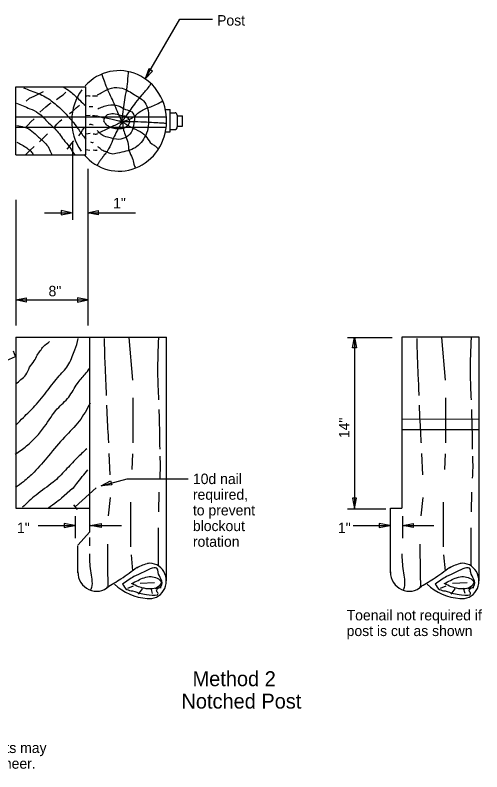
# Model space of a CAD drawing. Extents: x -0.7 to 88.8, y -25.9 to 22.
# Drawn here: x 70.1 to 76.35, y -25.09 to -14.95 of the extents above; entities that cross this region are included whole.
import ezdxf

# ---------------------------------------------------------------- set-up
doc = ezdxf.new("R2010")
doc.units = 0
doc.layers.add('Default', color=7, linetype='Continuous')

msp = doc.modelspace()

# ---------------------------------------------------------------- linework, layer by layer
at = {"layer": 'Default'}
for p, q in [((71.04331375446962, -16.823761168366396), (71.04331375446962, -15.91392783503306)), ((70.10589708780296, -15.914594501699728), (71.04431375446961, -15.914594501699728)), ((70.10589708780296, -16.823761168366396), (70.10589708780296, -15.914594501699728)), ((71.08914708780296, -16.177094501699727), (71.13923042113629, -16.175427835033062)), ((72.11214708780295, -16.216427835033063), (72.17239708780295, -16.216427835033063)), ((72.17239708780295, -16.516927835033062), (72.17239708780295, -16.216427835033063)), ((70.09814708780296, -16.314261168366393), (72.12131375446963, -16.314261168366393)), ((71.04739708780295, -16.29659450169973), (71.10381375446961, -16.29259450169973)), ((72.12489708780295, -16.311094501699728), (72.12489708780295, -16.311094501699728)), ((72.17239708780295, -16.259094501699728), (72.24081375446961, -16.259094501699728)), ((72.26614708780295, -16.29342783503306), (72.26739708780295, -16.446927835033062)), ((72.26614708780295, -16.299761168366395), (72.33731375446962, -16.299761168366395)), ((72.33731375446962, -16.43992783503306), (72.33731375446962, -16.299761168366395)), ((70.09814708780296, -16.452761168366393), (72.12131375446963, -16.452761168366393)), ((72.11214708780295, -16.516927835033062), (72.17239708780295, -16.516927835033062)), ((72.17239708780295, -16.483427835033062), (72.23198042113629, -16.483427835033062)), ((72.26731375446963, -16.43992783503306), (72.33731375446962, -16.43992783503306)), ((71.04739708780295, -16.54192783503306), (71.10148042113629, -16.533594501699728)), ((70.86614708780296, -16.658427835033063), (70.86614708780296, -17.693427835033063)), ((70.10589708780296, -16.823761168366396), (71.04331375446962, -16.823761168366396)), ((71.04331375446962, -16.754261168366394), (71.09964708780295, -16.760927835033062)), ((71.07373042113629, -17.009427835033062), (71.07373042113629, -18.68392783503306)), ((70.10589708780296, -17.42659450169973), (70.10589708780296, -18.68392783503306)), ((70.48964708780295, -17.598927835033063), (70.85448042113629, -17.598927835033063)), ((71.06806375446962, -17.598927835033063), (71.70896236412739, -17.598927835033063)), ((70.10589708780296, -18.68392783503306), (70.10589708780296, -19.109261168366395)), ((71.07373042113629, -18.68392783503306), (71.07373042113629, -19.109261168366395)), ((70.10698042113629, -18.767094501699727), (71.07373042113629, -18.767094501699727)), ((70.10556375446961, -19.26442783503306), (70.10556375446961, -21.55459450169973)), ((70.10556375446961, -19.26442783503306), (72.12564708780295, -19.26459450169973)), ((71.09181375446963, -19.26442783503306), (71.09181375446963, -21.876261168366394)), ((71.62181375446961, -19.27042783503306), (71.66898042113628, -19.843094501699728)), ((72.12564708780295, -22.53142783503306), (72.12564708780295, -19.26459450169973)), ((74.54789708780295, -19.269094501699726), (75.14773042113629, -19.269094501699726)), ((74.64239708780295, -19.269094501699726), (74.64239708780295, -20.435761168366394)), ((75.27839708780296, -19.26442783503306), (75.27839708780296, -21.55459450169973)), ((76.31223042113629, -19.26459450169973), (75.27839708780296, -19.26442783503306)), ((75.80839708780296, -19.27042783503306), (75.85556375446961, -19.843094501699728)), ((76.31223042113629, -22.53142783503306), (76.31223042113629, -19.26459450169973)), ((70.10106375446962, -19.522927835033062), (70.07406375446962, -19.453594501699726)), ((69.81464708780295, -19.649594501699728), (70.10414708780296, -19.523261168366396)), ((71.67639708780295, -20.076594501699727), (71.67639708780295, -20.681261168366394)), ((75.86298042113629, -20.076594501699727), (75.86298042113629, -20.681261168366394)), ((75.27839708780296, -20.363511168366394), (76.31331375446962, -20.360261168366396)), ((74.64239708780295, -20.435761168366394), (74.64239708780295, -20.69392783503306)), ((75.27839708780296, -20.504344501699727), (76.31273042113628, -20.50109450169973)), ((74.64239708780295, -20.69392783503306), (74.64239708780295, -21.56359450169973)), ((71.35281375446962, -20.823261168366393), (71.36514708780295, -21.110761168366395)), ((71.67148042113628, -20.830927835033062), (71.66231375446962, -21.040261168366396)), ((75.53939708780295, -20.823261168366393), (75.55173042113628, -21.110761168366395)), ((75.85806375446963, -20.830927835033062), (75.84889708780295, -21.040261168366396)), ((71.24931375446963, -21.257927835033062), (71.59981375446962, -21.165261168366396)), ((71.59981375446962, -21.165261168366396), (72.41406375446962, -21.165261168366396)), ((70.90231375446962, -21.539761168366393), (71.18273042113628, -21.28609450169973)), ((70.50306375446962, -21.290094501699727), (70.50306375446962, -21.290094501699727)), ((70.86789708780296, -21.295094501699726), (70.71998042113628, -21.422594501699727)), ((72.02456375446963, -21.341594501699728), (72.01689708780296, -21.606761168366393)), ((76.21114708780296, -21.341594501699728), (76.20348042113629, -21.606761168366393)), ((71.37106375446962, -21.415761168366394), (71.34573042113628, -21.65792783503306)), ((71.64281375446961, -21.47792783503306), (71.64281375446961, -22.07542783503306)), ((75.55764708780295, -21.415761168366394), (75.53231375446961, -21.65792783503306)), ((75.82939708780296, -21.47792783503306), (75.82939708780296, -22.07542783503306)), ((70.10556375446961, -21.55459450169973), (71.09714708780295, -21.55459450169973)), ((70.93364708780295, -21.57409450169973), (70.88273042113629, -21.51292783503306)), ((74.54789708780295, -21.56359450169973), (74.87214708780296, -21.56359450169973)), ((74.87214708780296, -21.56359450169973), (75.06131375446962, -21.56359450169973)), ((75.12389708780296, -22.345761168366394), (75.12389708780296, -21.55459450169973)), ((75.12389708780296, -21.55459450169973), (75.27839708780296, -21.55459450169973)), ((70.90173042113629, -21.662261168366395), (70.90173042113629, -21.958927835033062)), ((75.28431375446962, -21.662261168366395), (75.28431375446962, -21.958927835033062)), ((70.40514708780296, -21.789594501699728), (70.89456375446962, -21.789594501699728)), ((71.10806375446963, -21.789594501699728), (71.52239708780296, -21.789594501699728)), ((74.62473042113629, -21.789594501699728), (75.11414708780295, -21.789594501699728)), ((75.28931375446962, -21.789594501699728), (75.70364708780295, -21.789594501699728)), ((71.09181375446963, -21.876261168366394), (70.94406375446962, -22.04692783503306)), ((71.09181375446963, -21.94742783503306), (71.09181375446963, -22.061261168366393)), ((70.93731375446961, -22.345761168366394), (70.93731375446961, -22.05892783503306)), ((70.94406375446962, -22.054094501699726), (70.94406375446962, -22.04692783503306)), ((71.64998042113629, -22.181427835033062), (71.66973042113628, -22.395594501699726)), ((75.83656375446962, -22.181427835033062), (75.85631375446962, -22.395594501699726)), ((70.93731375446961, -22.424094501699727), (70.93731375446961, -22.345761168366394)), ((75.12389708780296, -22.424094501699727), (75.12389708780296, -22.345761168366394)), ((71.60914708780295, -22.630261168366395), (71.68314708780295, -22.594761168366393)), ((71.77048042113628, -22.559261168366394), (71.96531375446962, -22.552094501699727)), ((72.05264708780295, -22.54492783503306), (72.04673042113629, -22.510261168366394)), ((75.79573042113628, -22.630261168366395), (75.86973042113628, -22.594761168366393)), ((75.95706375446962, -22.559261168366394), (76.15189708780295, -22.552094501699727)), ((76.23923042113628, -22.54492783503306), (76.23331375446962, -22.510261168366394)), ((71.75023042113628, -22.70859450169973), (71.80406375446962, -22.637427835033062)), ((71.93839708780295, -22.701427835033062), (71.91823042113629, -22.630261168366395)), ((72.05339708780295, -22.62392783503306), (71.97273042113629, -22.631094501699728)), ((71.97273042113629, -22.631094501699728), (72.01231375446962, -22.630261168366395)), ((75.93681375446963, -22.70859450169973), (75.99064708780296, -22.637427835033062)), ((76.12498042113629, -22.701427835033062), (76.10481375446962, -22.630261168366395)), ((76.23998042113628, -22.62392783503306), (76.15931375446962, -22.631094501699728)), ((76.15931375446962, -22.631094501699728), (76.19889708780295, -22.630261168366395))]:
    msp.add_line(p, q, dxfattribs=at)
for points in [[(71.83831375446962, -15.805011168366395), (72.30406375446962, -15.006094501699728), (72.74331375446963, -15.006094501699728)], [(70.24564708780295, -16.104261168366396), (70.29156375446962, -16.066761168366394), (70.35206375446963, -16.035761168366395), (70.42514708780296, -16.00259450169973), (70.47739708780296, -15.973927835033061)], [(70.65273042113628, -16.08209450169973), (70.70706375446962, -16.04242783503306), (70.74048042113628, -16.01809450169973), (70.77806375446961, -15.98492783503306)], [(70.42931375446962, -16.25242783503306), (70.47114708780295, -16.217094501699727), (70.50873042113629, -16.17942783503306), (70.56089708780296, -16.137427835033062), (70.58173042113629, -16.126261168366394)], [(70.82823042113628, -16.272261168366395), (70.87206375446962, -16.23692783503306), (70.91589708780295, -16.194927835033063), (70.96189708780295, -16.157261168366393)], [(70.24348042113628, -16.446927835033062), (70.27064708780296, -16.422594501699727), (70.30823042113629, -16.382761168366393), (70.35206375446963, -16.342927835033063)], [(70.62564708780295, -16.45359450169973), (70.65689708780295, -16.413761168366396), (70.69873042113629, -16.371761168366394), (70.72381375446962, -16.35192783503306)], [(70.94931375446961, -16.568594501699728), (70.97639708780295, -16.533261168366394), (70.99948042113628, -16.49342783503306), (71.02656375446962, -16.455761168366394)], [(70.42514708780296, -16.65042783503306), (70.46689708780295, -16.603927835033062), (70.53173042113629, -16.544261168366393)], [(70.23306375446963, -16.827261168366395), (70.29573042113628, -16.765261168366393), (70.35206375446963, -16.712261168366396)], [(70.79689708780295, -16.747594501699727), (70.82606375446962, -16.71009450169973), (70.8512304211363, -16.672427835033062), (70.8824804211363, -16.63709450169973)]]:
    msp.add_lwpolyline(points, dxfattribs=at)
for points in [[(71.88875710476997, -15.67144669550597), (71.83831375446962, -15.805011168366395), (71.9362477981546, -15.701122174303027)], [(70.71448042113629, -17.62692783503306), (70.85448042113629, -17.598927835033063), (70.71448042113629, -17.57092783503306)], [(71.20806375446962, -17.62692783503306), (71.06806375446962, -17.598927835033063), (71.20806375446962, -17.57092783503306)], [(70.24698042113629, -18.79509450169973), (70.10698042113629, -18.767094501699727), (70.24698042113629, -18.73909450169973)], [(70.93373042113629, -18.795208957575), (71.07373042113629, -18.767208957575), (70.93373042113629, -18.739208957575)], [(74.61439708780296, -19.409094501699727), (74.64239708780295, -19.269094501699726), (74.67039708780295, -19.409094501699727)], [(71.39160823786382, -21.246253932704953), (71.24931375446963, -21.257927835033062), (71.37617254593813, -21.19242327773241)], [(74.61439708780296, -21.42359450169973), (74.64239708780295, -21.56359450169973), (74.67039708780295, -21.42359450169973)], [(70.75456375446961, -21.817594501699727), (70.89456375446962, -21.789594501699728), (70.75456375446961, -21.76159450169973)], [(71.24806375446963, -21.817594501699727), (71.10806375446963, -21.789594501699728), (71.24806375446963, -21.76159450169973)], [(74.97414708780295, -21.817594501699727), (75.11414708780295, -21.789594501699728), (74.97414708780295, -21.76159450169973)], [(75.42931375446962, -21.817594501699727), (75.28931375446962, -21.789594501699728), (75.42931375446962, -21.76159450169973)]]:
    msp.add_lwpolyline(points, close=True, dxfattribs=at)
for centre, major_axis, ratio, start_param, end_param in [((71.49134795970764, -16.369057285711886), (1.9067660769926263e-16, 0.6731102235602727), 0.9445438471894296, 2.3036393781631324, 7.079119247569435), ((71.49134795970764, -16.369057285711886), (1.9067660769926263e-16, 0.6731102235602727), 0.9445438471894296, 0.9008811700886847, 2.2143986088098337), ((72.23805967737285, -16.28938255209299), (8.495526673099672e-18, 0.029990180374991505), 0.9445438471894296, 4.574533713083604, 6.237265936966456), ((72.23916784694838, -16.288575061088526), (-4.793224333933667e-18, -0.0298063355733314), 0.9445438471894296, 1.4313513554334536, 1.4392111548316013), ((72.23693875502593, -16.451785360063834), (-5.240425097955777e-18, -0.03258722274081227), 0.9445438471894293, 6.0937818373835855, 8.002272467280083), ((71.97049453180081, -22.797490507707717), (1.4392587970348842e-16, 0.5080748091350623), 0.9445438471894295, 0.17943739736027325, 0.5303528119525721), ((71.89890567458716, -22.53128149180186), (6.704483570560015e-17, 0.23667593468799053), 0.9445438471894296, 2.997306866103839, 6.4059503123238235), ((76.15707786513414, -22.797490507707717), (1.4392587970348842e-16, 0.5080748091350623), 0.9445438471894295, 0.17943739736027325, 0.5303528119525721), ((76.08548900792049, -22.53128149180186), (6.704483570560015e-17, 0.23667593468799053), 0.9445438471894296, 2.997306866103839, 6.4059503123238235), ((71.18664795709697, -22.40607036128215), (-4.245406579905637e-17, -0.2639976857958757), 0.9445438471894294, 4.7265868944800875, 7.018322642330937), ((75.3732312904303, -22.40607036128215), (-4.245406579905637e-17, -0.2639976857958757), 0.9445438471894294, 4.7265868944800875, 7.018322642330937), ((71.91306372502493, -21.986540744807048), (-1.254338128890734e-16, -0.7800015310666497), 0.9445438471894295, 5.5640474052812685, 6.222034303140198), ((76.09964705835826, -21.986540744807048), (-1.254338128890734e-16, -0.7800015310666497), 0.9445438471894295, 5.5640474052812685, 6.222034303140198)]:
    msp.add_ellipse(centre, major_axis=major_axis, ratio=ratio, start_param=start_param, end_param=end_param, dxfattribs=at)
for points in [[(71.52981375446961, -16.369594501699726), (71.54023042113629, -16.278927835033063), (71.55698042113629, -16.148594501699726), (71.57781375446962, -16.024594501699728), (71.60289708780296, -15.872261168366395), (71.61123042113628, -15.772761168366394), (71.61748042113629, -15.708594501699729)], [(71.52773042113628, -16.37392783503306), (71.49014708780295, -16.294427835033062), (71.44623042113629, -16.188261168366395), (71.40039708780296, -16.08442783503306), (71.35231375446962, -15.98492783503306), (71.30848042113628, -15.876594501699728), (71.29589708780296, -15.838927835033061), (71.25831375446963, -15.74392783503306)], [(71.53189708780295, -16.371761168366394), (71.57989708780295, -16.31209450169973), (71.65089708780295, -16.212594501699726), (71.71573042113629, -16.124094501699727), (71.80123042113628, -16.01809450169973), (71.84514708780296, -15.967261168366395), (71.89314708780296, -15.907594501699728), (71.91606375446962, -15.869927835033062)], [(70.21014708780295, -15.927427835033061), (70.31239708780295, -15.96492783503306), (70.50239708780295, -16.04692783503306), (70.65273042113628, -16.157261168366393), (70.79689708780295, -16.29659450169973), (70.93048042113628, -16.460261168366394), (71.02656375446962, -16.590594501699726), (71.04706375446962, -16.61559450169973)], [(70.74048042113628, -15.914094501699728), (70.83448042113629, -15.973927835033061), (70.96398042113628, -16.093261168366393), (71.04414708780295, -16.16542783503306)], [(71.20198042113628, -16.020261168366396), (71.26881375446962, -15.982594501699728), (71.38781375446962, -15.929594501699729), (71.53189708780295, -15.931927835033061), (71.69689708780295, -16.01809450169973), (71.81589708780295, -16.09992783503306), (71.87231375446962, -16.197094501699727), (71.88481375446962, -16.33642783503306), (71.87639708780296, -16.471261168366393), (71.83264708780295, -16.588427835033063), (71.76573042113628, -16.679094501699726), (71.68431375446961, -16.740927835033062), (71.57989708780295, -16.77642783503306), (71.46931375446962, -16.802761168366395), (71.38781375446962, -16.811761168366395), (71.32314708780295, -16.785261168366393), (71.27298042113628, -16.767594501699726), (71.22281375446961, -16.72992783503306), (71.20398042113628, -16.716594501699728)], [(71.04739708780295, -16.03142783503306), (71.09756375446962, -16.03142783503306), (71.10389708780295, -16.03159450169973)], [(71.13523042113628, -16.03242783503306), (71.17481375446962, -16.033594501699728), (71.19989708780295, -16.03142783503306)], [(71.53398042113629, -16.37392783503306), (71.65298042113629, -16.33642783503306), (71.77206375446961, -16.24359450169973), (71.91398042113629, -16.17942783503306), (71.99548042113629, -16.144094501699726), (72.07481375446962, -16.102094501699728)], [(70.11648042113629, -16.133094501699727), (70.29573042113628, -16.205927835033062), (70.40848042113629, -16.26342783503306), (70.54414708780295, -16.39392783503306), (70.64448042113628, -16.486761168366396), (70.7634804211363, -16.643594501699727), (70.84706375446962, -16.749927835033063), (70.89498042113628, -16.818261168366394), (70.90339708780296, -16.825094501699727)], [(71.20398042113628, -16.208261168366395), (71.27089708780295, -16.17942783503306), (71.34606375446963, -16.15959450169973), (71.47964708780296, -16.166094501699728), (71.57573042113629, -16.214761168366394), (71.65931375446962, -16.24809450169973), (71.69689708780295, -16.340761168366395), (71.68639708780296, -16.40492783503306), (71.66556375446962, -16.499927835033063), (71.59248042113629, -16.581761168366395), (71.48806375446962, -16.61709450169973), (71.35439708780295, -16.592927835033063), (71.27298042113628, -16.564094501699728), (71.22498042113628, -16.526594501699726), (71.20198042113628, -16.499927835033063)], [(71.13523042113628, -16.29559450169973), (71.16231375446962, -16.298761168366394), (71.20198042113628, -16.298761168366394)], [(71.52773042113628, -16.376261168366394), (71.45048042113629, -16.365094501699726), (71.3794804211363, -16.347427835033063), (71.28756375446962, -16.329761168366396), (71.22914708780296, -16.31659450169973), (71.20823042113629, -16.30992783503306)], [(71.28756375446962, -16.376261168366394), (71.30223042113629, -16.318761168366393), (71.33556375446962, -16.285594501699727), (71.41498042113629, -16.272261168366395), (71.51106375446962, -16.292261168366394), (71.60706375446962, -16.32759450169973), (71.62798042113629, -16.387261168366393), (71.57573042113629, -16.45792783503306), (71.50473042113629, -16.475761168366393), (71.41914708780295, -16.471261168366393), (71.35439708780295, -16.444761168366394), (71.31056375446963, -16.40942783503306), (71.2917304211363, -16.376261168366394)], [(71.09506375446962, -16.416094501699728), (71.11223042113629, -16.413761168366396), (71.14181375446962, -16.420927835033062)], [(71.53398042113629, -16.376261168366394), (71.48806375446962, -16.455761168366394), (71.46089708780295, -16.506761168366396), (71.41289708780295, -16.603927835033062), (71.39198042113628, -16.656927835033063), (71.33348042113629, -16.769761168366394), (71.31264708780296, -16.800594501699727), (71.2917304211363, -16.825094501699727), (71.26256375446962, -16.86709450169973), (71.23331375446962, -16.904594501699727), (71.21448042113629, -16.93559450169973), (71.20198042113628, -16.95542783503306), (71.19573042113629, -16.959761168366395)], [(71.52773042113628, -16.37392783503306), (71.48381375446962, -16.40492783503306), (71.41706375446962, -16.435927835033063), (71.30848042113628, -16.48892783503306), (71.23123042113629, -16.524261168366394), (71.20198042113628, -16.53542783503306)], [(71.52773042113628, -16.376261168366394), (71.64256375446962, -16.449261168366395), (71.77206375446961, -16.513261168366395), (71.86181375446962, -16.592927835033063), (71.92656375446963, -16.674594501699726), (71.96831375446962, -16.70109450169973), (72.00589708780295, -16.73442783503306), (72.02264708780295, -16.743094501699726)], [(71.53189708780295, -16.376261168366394), (71.70106375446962, -16.37842783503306), (71.85764708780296, -16.382761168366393), (71.98714708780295, -16.391761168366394), (72.07273042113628, -16.39609450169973), (72.12281375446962, -16.40042783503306)], [(71.53189708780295, -16.376261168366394), (71.54656375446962, -16.471261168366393), (71.56948042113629, -16.555261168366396), (71.60706375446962, -16.654761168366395), (71.62381375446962, -16.769761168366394), (71.66556375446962, -16.864761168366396), (71.68848042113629, -16.946594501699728), (71.70939708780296, -17.00409450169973)], [(70.12181375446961, -16.430761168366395), (70.29981375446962, -16.48892783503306), (70.3854804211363, -16.56192783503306), (70.49206375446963, -16.656927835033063), (70.55048042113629, -16.73442783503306), (70.58598042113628, -16.811761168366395), (70.59639708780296, -16.827261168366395)], [(71.14306375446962, -16.54192783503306), (71.14348042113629, -16.54192783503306), (71.19364708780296, -16.544261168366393), (71.19989708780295, -16.54192783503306)], [(70.11964708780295, -16.652761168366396), (70.25606375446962, -16.732094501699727), (70.30614708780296, -16.77409450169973), (70.34164708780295, -16.825094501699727)], [(71.10606375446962, -16.65142783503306), (71.13098042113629, -16.656927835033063), (71.14748042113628, -16.655261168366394)], [(71.14348042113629, -16.756594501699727), (71.18314708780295, -16.760927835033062), (71.19781375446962, -16.75859450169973)], [(70.10689708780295, -19.895594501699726), (70.17598042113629, -19.834094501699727), (70.24131375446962, -19.77259450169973), (70.29223042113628, -19.668761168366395), (70.35398042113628, -19.584094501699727), (70.39389708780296, -19.50709450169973), (70.43389708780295, -19.44942783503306), (70.47748042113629, -19.391761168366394), (70.56039708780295, -19.325761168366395)], [(70.11048042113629, -20.441761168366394), (70.20864708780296, -20.341761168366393), (70.36123042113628, -20.18792783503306), (70.53556375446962, -19.97642783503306), (70.68814708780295, -19.784094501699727), (70.81889708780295, -19.622594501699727), (70.86248042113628, -19.52642783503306), (70.89889708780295, -19.43792783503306), (70.94131375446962, -19.285261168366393)], [(71.28931375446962, -19.28292783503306), (71.30014708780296, -19.635594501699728), (71.31356375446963, -19.92009450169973), (71.31798042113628, -20.047594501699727)], [(72.01723042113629, -19.275094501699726), (72.00564708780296, -19.742261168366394), (72.01806375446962, -20.10492783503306)], [(75.47589708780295, -19.28292783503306), (75.48673042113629, -19.635594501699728), (75.50014708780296, -19.92009450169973), (75.50456375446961, -20.047594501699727)], [(76.20381375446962, -19.275094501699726), (76.19223042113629, -19.742261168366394), (76.20464708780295, -20.10492783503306)], [(70.09964708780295, -20.834094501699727), (70.25223042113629, -20.722594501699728), (70.49198042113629, -20.464761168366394), (70.66264708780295, -20.22642783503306), (70.81531375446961, -20.068594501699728), (70.93156375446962, -19.88792783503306), (71.03698042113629, -19.761094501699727), (71.09248042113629, -19.686761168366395)], [(71.10314708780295, -20.149594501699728), (70.95539708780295, -20.39142783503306), (70.76056375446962, -20.60492783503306), (70.54548042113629, -20.853927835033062), (70.35064708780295, -21.074261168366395), (70.20956375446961, -21.20242783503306), (70.10198042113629, -21.280761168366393)], [(71.32248042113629, -20.175594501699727), (71.32698042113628, -20.304094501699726), (71.34714708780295, -20.674094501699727), (71.34748042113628, -20.68092783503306)], [(72.02256375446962, -20.23292783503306), (72.02573042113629, -20.32559450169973), (72.03431375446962, -20.766261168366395)], [(75.50906375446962, -20.175594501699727), (75.51356375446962, -20.304094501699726), (75.53373042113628, -20.674094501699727), (75.53406375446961, -20.68092783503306)], [(76.20914708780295, -20.23292783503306), (76.21231375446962, -20.32559450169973), (76.22089708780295, -20.766261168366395)], [(71.05614708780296, -20.76142783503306), (70.92173042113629, -20.88942783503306), (70.77389708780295, -21.045927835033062), (70.60589708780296, -21.20942783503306), (70.37748042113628, -21.380261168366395), (70.19614708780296, -21.54542783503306)], [(72.03614708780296, -20.858594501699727), (72.03923042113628, -21.015594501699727), (72.03439708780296, -21.152761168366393)], [(76.22273042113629, -20.858594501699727), (76.22581375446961, -21.015594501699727), (76.22098042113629, -21.152761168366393)], [(70.86789708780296, -21.295094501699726), (70.92431375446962, -21.22642783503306), (71.07031375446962, -21.041761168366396)], [(70.54639708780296, -21.553427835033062), (70.65539708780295, -21.468594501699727), (70.71998042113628, -21.422594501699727)], [(72.01306375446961, -21.820261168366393), (72.01306375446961, -22.033594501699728), (72.01306375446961, -22.282594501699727), (72.01306375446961, -22.325261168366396)], [(76.19964708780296, -21.820261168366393), (76.19964708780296, -22.033594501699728), (76.19964708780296, -22.282594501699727), (76.19964708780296, -22.325261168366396)], [(71.33364708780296, -22.039927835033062), (71.33364708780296, -22.210594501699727), (71.34039708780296, -22.594761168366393)], [(75.52023042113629, -22.039927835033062), (75.52023042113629, -22.210594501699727), (75.52698042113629, -22.594761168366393)], [(71.09181375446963, -22.167927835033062), (71.09181375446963, -22.189261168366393), (71.11189708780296, -22.424094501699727), (71.11189708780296, -22.64459450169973), (71.10523042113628, -22.658761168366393)], [(75.27839708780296, -22.167927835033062), (75.27839708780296, -22.189261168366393), (75.29848042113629, -22.424094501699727), (75.29848042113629, -22.64459450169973), (75.29181375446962, -22.658761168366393)], [(71.32698042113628, -22.616094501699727), (71.51506375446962, -22.502261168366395), (71.73331375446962, -22.346094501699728)], [(71.53531375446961, -22.573427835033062), (71.68981375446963, -22.473761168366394), (71.82423042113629, -22.409761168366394), (72.00564708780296, -22.374261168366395), (72.01306375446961, -22.417761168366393), (72.05339708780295, -22.510261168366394), (72.05339708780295, -22.602594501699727), (71.99298042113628, -22.65959450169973), (72.01231375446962, -22.701427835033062), (71.89131375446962, -22.715594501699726), (71.78389708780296, -22.701427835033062), (71.66973042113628, -22.66592783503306), (71.59573042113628, -22.64459450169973), (71.53531375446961, -22.573427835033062)], [(75.51356375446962, -22.616094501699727), (75.70164708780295, -22.502261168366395), (75.91989708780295, -22.346094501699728)], [(75.72189708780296, -22.573427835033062), (75.87639708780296, -22.473761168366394), (76.01081375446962, -22.409761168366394), (76.19223042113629, -22.374261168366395), (76.19964708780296, -22.417761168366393), (76.23998042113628, -22.510261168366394), (76.23998042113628, -22.602594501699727), (76.17956375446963, -22.65959450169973), (76.19889708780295, -22.701427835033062), (76.07789708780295, -22.715594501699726), (75.97048042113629, -22.701427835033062), (75.85631375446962, -22.66592783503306), (75.78231375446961, -22.64459450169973), (75.72189708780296, -22.573427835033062)], [(71.65623042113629, -22.566261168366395), (71.74356375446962, -22.523594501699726), (71.82423042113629, -22.487927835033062), (71.91823042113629, -22.473761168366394), (71.99889708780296, -22.49509450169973), (72.05264708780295, -22.54492783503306), (72.02573042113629, -22.60192783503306), (71.93839708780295, -22.637427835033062), (71.82423042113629, -22.630261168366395), (71.75023042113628, -22.60892783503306), (71.66289708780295, -22.566261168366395)], [(75.84281375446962, -22.566261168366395), (75.93014708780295, -22.523594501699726), (76.01081375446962, -22.487927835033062), (76.10481375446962, -22.473761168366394), (76.18548042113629, -22.49509450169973), (76.23923042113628, -22.54492783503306), (76.21231375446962, -22.60192783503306), (76.12498042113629, -22.637427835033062), (76.01081375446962, -22.630261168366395), (75.93681375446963, -22.60892783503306), (75.84948042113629, -22.566261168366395)]]:
    msp.add_spline(points, degree=3, dxfattribs=at)

# ---------------------------------------------------------------- texts
for s, height, p in [('Post', 0.13999999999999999, (72.80267767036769, -15.092495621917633)), ('1"', 0.13999999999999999, (71.40994991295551, -17.539998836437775)), ('8" ', 0.13999999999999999, (70.54544113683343, -18.71873325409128)), ('10d nail ', 0.13999999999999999, (72.47874736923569, -21.233857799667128)), ('required, ', 0.13999999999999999, (72.47874736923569, -21.44385779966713)), ('to prevent ', 0.13999999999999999, (72.47874736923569, -21.653857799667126)), ('1"', 0.13999999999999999, (70.12325142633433, -21.889279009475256)), ('blockout ', 0.13999999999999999, (72.47874736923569, -21.863857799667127)), ('1" ', 0.13999999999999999, (74.42186748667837, -21.889279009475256)), ('rotation', 0.13999999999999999, (72.47874736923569, -22.073857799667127)), ('Toenail not required if', 0.13999999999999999, (74.53784741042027, -23.059740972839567)), ('post is cut as shown', 0.13999999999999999, (74.53784741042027, -23.269740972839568)), ('  Method 2', 0.19999999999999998, (72.32531203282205, -23.941090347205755)), ('Notched Post', 0.19999999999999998, (72.32531203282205, -24.241090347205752)), ('Alternate methods of placing the Blockouts on round Posts may', 0.13999999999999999, (65.25332660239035, -24.83660387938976)), ('be submitted for consideration and approved by the Engineer.', 0.13999999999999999, (65.25332660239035, -25.04660387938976))]:
    msp.add_text(s, height=height, dxfattribs=at).set_placement(p)
msp.add_text('14" ', height=0.13999999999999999, rotation=89.99999999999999, dxfattribs=at).set_placement((74.57538525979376, -20.618534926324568))

doc.saveas('drawing.dxf')
